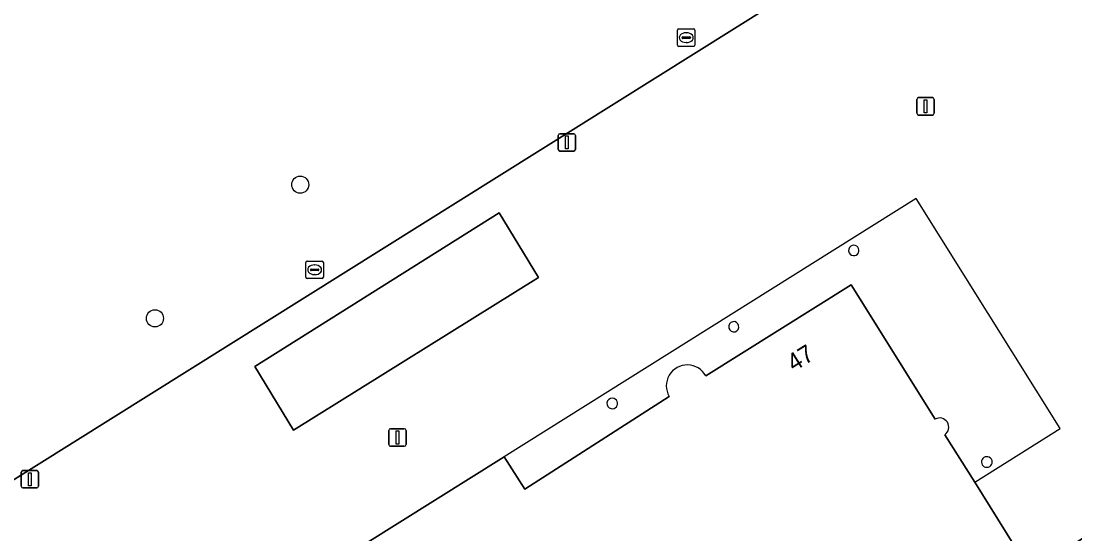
# Model space of a CAD drawing. Extents: x 159279 to 160377, y 384531 to 385888.
# Drawn here: x 159404.1 to 159464.5, y 385344 to 385373.4 of the extents above; entities that cross this region are included whole.
import ezdxf

# ---------------------------------------------------------------- set-up
doc = ezdxf.new("R2010")
doc.units = 0
for name, color, linetype in [('IMGEO_Boom', 7, 'Continuous'), ('IMGEO_Groenvoorziening', 7, 'Continuous'), ('IMGEO_Kolk', 7, 'Continuous'), ('IMGEO_Lichtmast', 7, 'Continuous'), ('IMGEO_Pand', 7, 'Continuous'), ('IMGEO_Pand_nummerreeks', 7, 'Continuous'), ('IMGEO_Pand_overbouw', 7, 'Continuous'), ('IMGEO_Voetgangersgebied_open', 7, 'Continuous')]:
    doc.layers.add(name, color=color, linetype=linetype)

msp = doc.modelspace()

# ---------------------------------------------------------------- linework, layer by layer
at = {"layer": 'IMGEO_Boom'}
for centre in [(159420.082, 385364.006), (159411.747, 385356.339)]:
    msp.add_circle(centre, 0.489, dxfattribs=at)
at = {"layer": 'IMGEO_Groenvoorziening'}
msp.add_lwpolyline([(159366.933, 385321.453), (159368.853, 385322.693), (159367.822, 385324.378), (159372.867, 385327.564), (159374.917, 385324.392), (159380.243, 385327.744), (159378.085, 385331.09), (159453.794, 385378.488), (159453.246, 385379.369)], dxfattribs=at)
at = {"layer": 'IMGEO_Kolk'}
for p, q in [((159441.731, 385372.015), (159441.731, 385372.867)), ((159441.806, 385372.941), (159442.658, 385372.941)), ((159442.219, 385372.721), (159442.244, 385372.721)), ((159442.732, 385372.867), (159442.732, 385372.015)), ((159441.99, 385372.435), (159441.99, 385372.447)), ((159442.428, 385372.398), (159442.03, 385372.398)), ((159442.033, 385372.484), (159442.431, 385372.484)), ((159442.242, 385372.161), (159442.217, 385372.161)), ((159442.474, 385372.447), (159442.474, 385372.435)), ((159442.658, 385371.941), (159441.806, 385371.941)), ((159420.408, 385358.699), (159420.408, 385359.551)), ((159420.483, 385359.625), (159421.335, 385359.625)), ((159420.896, 385359.405), (159420.921, 385359.405)), ((159421.409, 385359.551), (159421.409, 385358.699)), ((159420.667, 385359.119), (159420.667, 385359.131)), ((159421.105, 385359.082), (159420.707, 385359.082)), ((159420.71, 385359.168), (159421.108, 385359.168)), ((159420.919, 385358.845), (159420.894, 385358.845)), ((159421.151, 385359.131), (159421.151, 385359.119)), ((159421.335, 385358.625), (159420.483, 385358.625))]:
    msp.add_line(p, q, dxfattribs=at)
for points in [[(159441.731, 385372.015), (159441.731, 385372.867)], [(159441.806, 385372.941), (159442.658, 385372.941)], [(159442.732, 385372.867), (159442.732, 385372.015)], [(159442.658, 385371.941), (159441.806, 385371.941)], [(159420.408, 385358.699), (159420.408, 385359.551)], [(159420.483, 385359.625), (159421.335, 385359.625)], [(159421.409, 385359.551), (159421.409, 385358.699)], [(159421.335, 385358.625), (159420.483, 385358.625)]]:
    msp.add_lwpolyline(points, dxfattribs=at)
for centre, radius, start, end in [((159441.808, 385372.865), 0.0765, 91.55205, 178.44795), ((159441.808, 385372.865), 0.0765, 91.55205, 178.44795), ((159442.656, 385372.865), 0.0765, 1.55205, 88.44795), ((159442.656, 385372.865), 0.0765, 1.55205, 88.44795), ((159441.808, 385372.017), 0.0765, 181.55205, 268.44795), ((159441.808, 385372.017), 0.0765, 181.55205, 268.44795), ((159442.03, 385372.444), 0.0403, 85.87752, 175.75265), ((159442.027, 385372.434), 0.0366, 178.93798, 274.71019), ((159442.431, 385372.441), 0.043, 264.86636, 352.45326), ((159442.435, 385372.446), 0.0386, 1.73085, 96.63898), ((159442.656, 385372.017), 0.0765, 271.55205, 358.44795), ((159442.656, 385372.017), 0.0765, 271.55205, 358.44795), ((159420.485, 385359.549), 0.0765, 91.55205, 178.44795), ((159420.485, 385359.549), 0.0765, 91.55205, 178.44795), ((159421.333, 385359.549), 0.0765, 1.55205, 88.44795), ((159421.333, 385359.549), 0.0765, 1.55205, 88.44795), ((159420.485, 385358.701), 0.0765, 181.55205, 268.44795), ((159420.485, 385358.701), 0.0765, 181.55205, 268.44795), ((159420.707, 385359.128), 0.0403, 85.87752, 175.75265), ((159420.704, 385359.118), 0.0366, 178.93798, 274.71019), ((159421.108, 385359.125), 0.043, 264.86636, 352.45326), ((159421.112, 385359.13), 0.0386, 1.73085, 96.63898), ((159421.333, 385358.701), 0.0765, 271.55205, 358.44795), ((159421.333, 385358.701), 0.0765, 271.55205, 358.44795)]:
    msp.add_arc(centre, radius, start, end, dxfattribs=at)
for centre, major_axis, ratio, start_param, end_param in [((159442.218, 385372.441), (-0.387, 0.002), 0.722429, 4.712389, 7.853982), ((159442.243, 385372.441), (-0.39, 0.002), 0.717154, 1.570796, 4.712389), ((159420.895, 385359.125), (-0.387, 0.002), 0.722429, 4.712389, 7.853982), ((159420.92, 385359.125), (-0.39, 0.002), 0.717154, 1.570796, 4.712389)]:
    msp.add_ellipse(centre, major_axis=major_axis, ratio=ratio, start_param=start_param, end_param=end_param, dxfattribs=at)
at = {"layer": 'IMGEO_Lichtmast'}
for p, q in [((159455.565, 385369), (159456.355, 385369)), ((159456.355, 385369), (159455.565, 385369)), ((159455.465, 385368.1), (159455.465, 385368.9)), ((159455.465, 385368.9), (159455.465, 385368.1)), ((159456.455, 385368.9), (159456.455, 385368.1)), ((159456.455, 385368.1), (159456.455, 385368.9)), ((159456.355, 385368), (159455.565, 385368)), ((159455.565, 385368), (159456.355, 385368)), ((159434.881, 385366.03), (159434.881, 385366.83)), ((159434.881, 385366.83), (159434.881, 385366.03)), ((159434.981, 385366.93), (159435.771, 385366.93)), ((159435.771, 385366.93), (159434.981, 385366.93)), ((159435.871, 385366.83), (159435.871, 385366.03)), ((159435.871, 385366.03), (159435.871, 385366.83)), ((159435.771, 385365.93), (159434.981, 385365.93)), ((159434.981, 385365.93), (159435.771, 385365.93)), ((159425.162, 385349.105), (159425.162, 385349.905)), ((159425.162, 385349.905), (159425.162, 385349.105)), ((159425.262, 385350.005), (159426.052, 385350.005)), ((159426.052, 385350.005), (159425.262, 385350.005)), ((159426.152, 385349.905), (159426.152, 385349.105)), ((159426.152, 385349.105), (159426.152, 385349.905)), ((159426.052, 385349.005), (159425.262, 385349.005)), ((159425.262, 385349.005), (159426.052, 385349.005)), ((159404.071, 385346.71), (159404.071, 385347.51)), ((159404.071, 385347.51), (159404.071, 385346.71)), ((159404.171, 385347.61), (159404.961, 385347.61)), ((159404.961, 385347.61), (159404.171, 385347.61)), ((159405.061, 385347.51), (159405.061, 385346.71)), ((159405.061, 385346.71), (159405.061, 385347.51)), ((159404.961, 385346.61), (159404.171, 385346.61)), ((159404.171, 385346.61), (159404.961, 385346.61))]:
    msp.add_line(p, q, dxfattribs=at)
for points in [[(159455.885, 385368.875), (159456.035, 385368.875), (159456.035, 385368.125), (159455.885, 385368.125), (159455.885, 385368.875)], [(159435.301, 385366.805), (159435.451, 385366.805), (159435.451, 385366.055), (159435.301, 385366.055), (159435.301, 385366.805)], [(159425.582, 385349.88), (159425.732, 385349.88), (159425.732, 385349.13), (159425.582, 385349.13), (159425.582, 385349.88)], [(159404.491, 385347.485), (159404.641, 385347.485), (159404.641, 385346.735), (159404.491, 385346.735), (159404.491, 385347.485)]]:
    msp.add_lwpolyline(points, dxfattribs=at)
for centre, start, end in [((159455.565, 385368.9), 90, 180), ((159455.565, 385368.9), 90, 180), ((159456.355, 385368.9), 0, 90), ((159456.355, 385368.9), 360, 90), ((159455.565, 385368.1), 180, 270), ((159455.565, 385368.1), 180, 270), ((159456.355, 385368.1), 270, 0), ((159456.355, 385368.1), 270, 0), ((159434.981, 385366.83), 90, 180), ((159434.981, 385366.83), 90, 180), ((159435.771, 385366.83), 0, 90), ((159435.771, 385366.83), 360, 90), ((159434.981, 385366.03), 180, 270), ((159434.981, 385366.03), 180, 270), ((159435.771, 385366.03), 270, 0), ((159435.771, 385366.03), 270, 0), ((159425.262, 385349.905), 90, 180), ((159425.262, 385349.905), 90, 180), ((159426.052, 385349.905), 0, 90), ((159426.052, 385349.905), 360, 90), ((159425.262, 385349.105), 180, 270), ((159425.262, 385349.105), 180, 270), ((159426.052, 385349.105), 270, 0), ((159426.052, 385349.105), 270, 0), ((159404.171, 385347.51), 90, 180), ((159404.171, 385347.51), 90, 180), ((159404.961, 385347.51), 0, 90), ((159404.961, 385347.51), 360, 90), ((159404.171, 385346.71), 180, 270), ((159404.171, 385346.71), 180, 270), ((159404.961, 385346.71), 270, 0), ((159404.961, 385346.71), 270, 0)]:
    msp.add_arc(centre, 0.1, start, end, dxfattribs=at)
at = {"layer": 'IMGEO_Pand'}
msp.add_lwpolyline([(159433.757, 385358.677), (159431.49, 385362.391), (159417.47, 385353.572), (159419.691, 385349.923)], close=True, dxfattribs=at)
for points in [[(159456.51, 385350.561), (159451.688, 385358.261), (159443.348, 385353.038)], [(159441.25, 385351.859), (159432.968, 385346.545), (159431.78, 385348.397), (159415.867, 385338.438), (159394.563, 385325.104), (159402.485, 385312.665), (159400.596, 385311.48), (159430.445, 385263.896), (159444.541, 385272.72), (159445.724, 385270.83), (159492.501, 385300.115)], [(159492.501, 385300.115), (159484.487, 385312.598), (159486.385, 385313.787), (159466.895, 385344.913), (159461.972, 385341.84), (159458.781, 385346.947), (159457.065, 385349.663)]]:
    msp.add_lwpolyline(points, dxfattribs=at)
for centre, radius, start, end in [((159451.845, 385360.234), 0.3, 106.60724, 264.87193), ((159451.844, 385360.234), 0.3, 264.98618, 106.49299), ((159444.968, 385355.856), 0.299, 80.75829, 260.75829), ((159444.943, 385355.86), 0.3, 265.61755, 75.89902), ((159442.29, 385352.464), 1.203, 28.49887, 210.16995), ((159437.976, 385351.456), 0.299, 83.88111, 259.96709), ((159437.988, 385351.454), 0.3, 257.64711, 86.2011), ((159456.763, 385350.097), 0.529, 304.79491, 118.64055), ((159459.467, 385348.099), 0.3, 90.69582, 274.27498), ((159459.491, 385348.1), 0.3, 269.59694, 95.37387)]:
    msp.add_arc(centre, radius, start, end, dxfattribs=at)
at = {"layer": 'IMGEO_Pand_overbouw'}
for points in [[(159463.678, 385350.025), (159455.422, 385363.205), (159431.78, 385348.397), (159432.968, 385346.545), (159441.25, 385351.859)], [(159443.348, 385353.038), (159451.688, 385358.261), (159456.51, 385350.561)], [(159457.065, 385349.663), (159458.781, 385346.947), (159463.678, 385350.025)]]:
    msp.add_lwpolyline(points, dxfattribs=at)
for centre, radius, start, end in [((159442.29, 385352.464), 1.203, 28.49887, 210.16995), ((159456.763, 385350.097), 0.529, 304.79491, 118.64055)]:
    msp.add_arc(centre, radius, start, end, dxfattribs=at)
at = {"layer": 'IMGEO_Voetgangersgebied_open'}
for points in [[(159389.39, 385321.78), (159429.394, 385258.118), (159424.986, 385255.303), (159426.009, 385253.608), (159497.859, 385298.653), (159506.85, 385304.364), (159515.25, 385309.623), (159513.073, 385313.056), (159512.632, 385312.774), (159509.325, 385318.031), (159509.752, 385318.295), (159473.614, 385375.297), (159467.362, 385385.157), (159464.704, 385383.64), (159463.396, 385385.729), (159461.661, 385384.66), (159457.508, 385382.049), (159453.622, 385379.606), (159453.246, 385379.369), (159453.794, 385378.488), (159378.085, 385331.09)], [(159443.348, 385353.038), (159451.688, 385358.261), (159456.51, 385350.561)], [(159389.627, 385328.658), (159412.886, 385343.296), (159415.867, 385338.438), (159431.78, 385348.397), (159432.968, 385346.545), (159441.25, 385351.859)], [(159457.065, 385349.663), (159458.781, 385346.947), (159461.972, 385341.84), (159466.895, 385344.913), (159486.385, 385313.787), (159484.487, 385312.598), (159492.501, 385300.115), (159445.724, 385270.83), (159444.541, 385272.72), (159430.445, 385263.896), (159400.596, 385311.48)]]:
    msp.add_lwpolyline(points, dxfattribs=at)
msp.add_lwpolyline([(159417.47, 385353.572), (159431.49, 385362.391), (159433.757, 385358.677), (159419.691, 385349.923)], close=True, dxfattribs=at)
for centre, radius, start, end in [((159451.845, 385360.234), 0.3, 106.60724, 264.87193), ((159451.844, 385360.234), 0.3, 264.98618, 106.49299), ((159444.968, 385355.856), 0.299, 80.75829, 260.75829), ((159444.943, 385355.86), 0.3, 265.61755, 75.89902), ((159442.29, 385352.464), 1.203, 28.49887, 210.16995), ((159437.976, 385351.456), 0.299, 83.88111, 259.96709), ((159437.988, 385351.454), 0.3, 257.64711, 86.2011), ((159456.763, 385350.097), 0.529, 304.79491, 118.64055), ((159459.467, 385348.099), 0.3, 90.69582, 274.27498), ((159459.491, 385348.1), 0.3, 269.59694, 95.37387)]:
    msp.add_arc(centre, radius, start, end, dxfattribs=at)

# ---------------------------------------------------------------- texts
at = {"layer": 'IMGEO_Pand_nummerreeks'}
msp.add_text('47', height=1, rotation=32.05699, dxfattribs=at).set_placement((159448.406, 385353.256))

doc.saveas('drawing.dxf')
